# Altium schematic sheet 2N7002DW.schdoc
size 127 x 101 mm
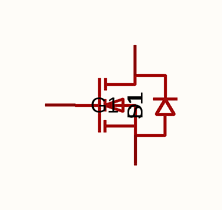
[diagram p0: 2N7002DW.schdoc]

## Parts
Q?  2n7002dw k72  [SC-70-6_L2.2-W1.3-P0.65-LS2.1-BR]  (value not drawn)  (part A of 2)

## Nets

Not connected (* = marked no-connect by the designer): Q? 3(D1) 4(S1) 5(G1)

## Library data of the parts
Q? = 2n7002dw k72: 数量:2个N沟道;漏源电压(Vdss):60V;连续漏极电流(Id):115mA;导通电阻(RDS(on)):5Ω@10V;耗散功率(Pd):150mW;阈值电压(Vgs(th)):2.5V;; Manufacturer: CJ(江苏长电/长晶); AddInBom: yes; ModelId: 7779600a2eb94c6fae04993c10cd58cb; ModelName: SC-70-6_L2.0-W1.3-H1.0-P0.65; ModelTransform: 82.677,78.74,0,0,0,0,0,0,0; Number: 2个N沟道; Drain to Source Voltage: 60V; Current - Continuous Drain(Id): 115mA; RDS(on): 5Ω@10V; Pd - Power Dissipation: 150mW; Gate Threshold Voltage (Vgs(th)): 2.5V; Input Capacitance(Ciss): 50pF; Reverse Transfer Capacitance (Crss@Vds): 5pF; Type: N沟道; Output Capacitance(Coss): 25pF; Vgs: ±20V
